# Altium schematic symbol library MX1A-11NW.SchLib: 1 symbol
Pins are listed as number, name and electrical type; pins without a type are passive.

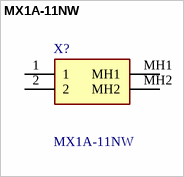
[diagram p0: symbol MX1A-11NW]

## MX1A-11NW
designator X?
CHERRY - MX1A-11NW - Tactile Switch, MX Series, Top Actuated, Surface Mount, Plunger for Cap, 59.5 gf, 10mA at 12VDC; Geometry.Height: 15.2mm
footprint MX1A11NW
pins: 1, 2, MH1, MH2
